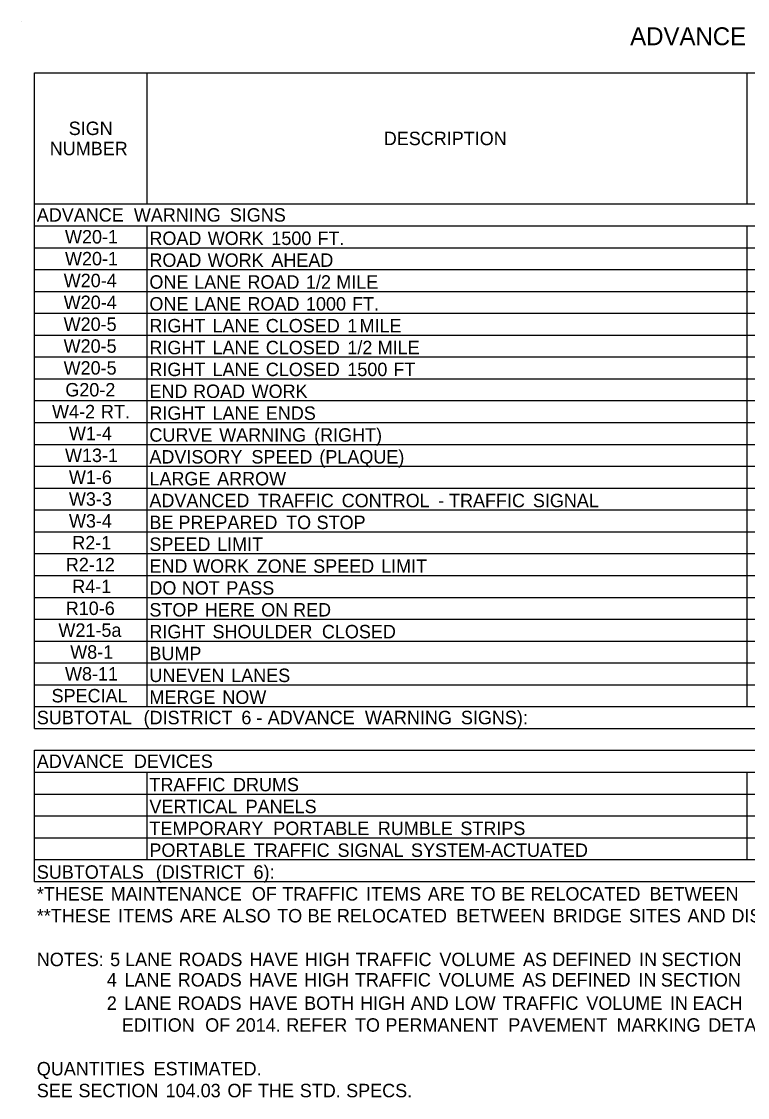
# Model space of a CAD drawing. Extents: x 542596 to 1930787, y -1948294 to 596640.
# Drawn here: x 544502.6 to 544826.4, y -1945630.8 to -1945150.8 of the extents above; entities that cross this region are included whole.
import ezdxf

# ---------------------------------------------------------------- set-up
doc = ezdxf.new("R2010")
doc.units = 0
doc.layers.add('Default', color=7, linetype='Continuous')

msp = doc.modelspace()

# ---------------------------------------------------------------- linework, layer by layer
at = {"layer": 'Default'}
for p, q in [((544502.61, -1945150.75), (544502.61, -1945150.75)), ((544508.46, -1945173.66), (545412.28, -1945173.66)), ((544508.46, -1945466.16), (544508.46, -1945173.66)), ((544508.46, -1945466.16), (544508.46, -1945173.66)), ((544558.67, -1945232.16), (544558.67, -1945173.66)), ((544826.31, -1945232.16), (544826.31, -1945173.66)), ((544508.46, -1945232.16), (545412.28, -1945232.16)), ((544508.46, -1945241.91), (545412.28, -1945241.91)), ((544558.67, -1945456.41), (544558.67, -1945241.91)), ((544558.67, -1945456.41), (544558.67, -1945241.91)), ((544826.31, -1945456.41), (544826.31, -1945241.91)), ((544826.31, -1945456.41), (544826.31, -1945241.91)), ((544508.46, -1945251.66), (545412.28, -1945251.66)), ((544508.46, -1945261.41), (545412.28, -1945261.41)), ((544508.46, -1945271.16), (545412.28, -1945271.16)), ((544508.46, -1945280.91), (545412.28, -1945280.91)), ((544508.46, -1945290.66), (545412.28, -1945290.66)), ((544508.46, -1945300.41), (545412.28, -1945300.41)), ((544508.46, -1945310.16), (545412.28, -1945310.16)), ((544508.46, -1945319.91), (545412.28, -1945319.91)), ((544508.46, -1945329.66), (545412.28, -1945329.66)), ((544508.46, -1945339.41), (545412.28, -1945339.41)), ((544508.46, -1945349.16), (545412.28, -1945349.16)), ((544508.46, -1945358.91), (545412.28, -1945358.91)), ((544508.46, -1945368.66), (545412.28, -1945368.66)), ((544508.46, -1945378.41), (545412.28, -1945378.41)), ((544508.46, -1945388.16), (545412.28, -1945388.16)), ((544508.46, -1945397.91), (545412.28, -1945397.91)), ((544508.46, -1945407.66), (545412.28, -1945407.66)), ((544508.46, -1945417.41), (545412.28, -1945417.41)), ((544508.46, -1945427.16), (545412.28, -1945427.16)), ((544508.46, -1945436.91), (545412.28, -1945436.91)), ((544508.46, -1945446.66), (545412.28, -1945446.66)), ((544508.46, -1945456.41), (545412.28, -1945456.41)), ((544508.46, -1945466.16), (545412.28, -1945466.16)), ((544508.46, -1945475.91), (545412.28, -1945475.91)), ((544508.46, -1945534.41), (544508.46, -1945475.91)), ((544508.46, -1945534.41), (544508.46, -1945475.91)), ((544558.67, -1945475.91), (545324.53, -1945475.91)), ((544508.46, -1945485.66), (545412.28, -1945485.66)), ((544558.67, -1945524.66), (544558.67, -1945485.66)), ((544558.67, -1945524.66), (544558.67, -1945485.66)), ((544826.31, -1945524.66), (544826.31, -1945485.66)), ((544826.31, -1945524.66), (544826.31, -1945485.66)), ((544508.46, -1945495.41), (545412.28, -1945495.41)), ((544508.46, -1945505.16), (545412.28, -1945505.16)), ((544508.46, -1945514.91), (545412.28, -1945514.91)), ((544508.46, -1945524.66), (545412.28, -1945524.66)), ((544508.46, -1945524.66), (545412.28, -1945524.66)), ((544508.46, -1945534.41), (545412.28, -1945534.41))]:
    msp.add_line(p, q, dxfattribs=at)

# ---------------------------------------------------------------- texts
for s, height, p in [('ADVANCE', 8, (544774.08, -1945161.33)), ('SIGN', 6, (544523.65, -1945201.41)), ('DESCRIPTION', 6, (544664.18, -1945205.91)), ('NUMBER', 6, (544515.19, -1945210.41)), ('ADVANCE', 6, (544509.43, -1945240.04)), (' WARNING', 6, (544550.48, -1945240.04)), (' SIGNS', 6, (544593.28, -1945240.04)), ('W20-1', 6, (544522, -1945249.79)), ('ROAD', 6, (544559.65, -1945250.46)), (' WORK', 6, (544583.42, -1945250.46)), (' 1500', 6, (544611.81, -1945250.46)), (' FT.', 6, (544632.38, -1945250.46)), ('W20-1', 6, (544522, -1945259.54)), ('ROAD', 6, (544559.65, -1945260.21)), (' WORK', 6, (544583.42, -1945260.21)), (' AHEAD', 6, (544611.81, -1945260.21)), ('W20-4', 6, (544521.43, -1945269.29)), ('ONE', 6, (544559.65, -1945269.96)), (' LANE', 6, (544577.37, -1945269.96)), (' ROAD', 6, (544601.15, -1945269.96)), (' 1/2', 6, (544627.25, -1945269.96)), (' MILE', 6, (544640.78, -1945269.96)), ('W20-4', 6, (544521.43, -1945279.04)), ('ONE', 6, (544559.65, -1945279.71)), (' LANE', 6, (544577.37, -1945279.71)), (' ROAD', 6, (544601.15, -1945279.71)), (' 1000', 6, (544627.25, -1945279.71)), (' FT.', 6, (544647.82, -1945279.71)), ('W20-5', 6, (544521.39, -1945288.79)), ('RIGHT', 6, (544559.65, -1945289.46)), (' LANE', 6, (544585.56, -1945289.46)), (' CLOSED', 6, (544609.34, -1945289.46)), (' 1', 6, (544645.7, -1945289.46)), (' MILE', 6, (544651.14, -1945289.46)), ('W20-5', 6, (544521.39, -1945298.54)), ('RIGHT', 6, (544559.65, -1945299.21)), (' LANE', 6, (544585.56, -1945299.21)), (' CLOSED', 6, (544609.34, -1945299.21)), (' 1/2', 6, (544645.7, -1945299.21)), (' MILE', 6, (544659.23, -1945299.21)), ('W20-5', 6, (544521.39, -1945308.29)), ('RIGHT', 6, (544559.65, -1945308.96)), (' LANE', 6, (544585.56, -1945308.96)), (' CLOSED', 6, (544609.34, -1945308.96)), (' 1500', 6, (544645.7, -1945308.96)), (' FT', 6, (544666.26, -1945308.96)), ('G20-2', 6, (544522.14, -1945318.04)), ('END', 6, (544559.65, -1945318.71)), (' ROAD', 6, (544576.9, -1945318.71)), (' WORK', 6, (544603.01, -1945318.71)), ('W4-2', 6, (544516.23, -1945327.79)), (' RT.', 6, (544535.8, -1945327.79)), ('RIGHT', 6, (544559.65, -1945328.46)), (' LANE', 6, (544585.56, -1945328.46)), (' ENDS', 6, (544609.34, -1945328.46)), ('W1-4', 6, (544523.76, -1945337.54)), ('CURVE', 6, (544559.65, -1945338.21)), (' WARNING', 6, (544588.55, -1945338.21)), (' (RIGHT)', 6, (544630.87, -1945338.21)), ('W13-1', 6, (544522, -1945347.29)), ('ADVISORY', 6, (544559.65, -1945347.96)), (' SPEED', 6, (544602.91, -1945347.96)), (' (PLAQUE)', 6, (544633.22, -1945347.96)), ('W1-6', 6, (544523.74, -1945357.04)), ('LARGE', 6, (544559.65, -1945357.71)), (' ARROW', 6, (544587.62, -1945357.71)), ('W3-3', 6, (544523.74, -1945366.79)), ('ADVANCED', 6, (544559.65, -1945367.46)), (' TRAFFIC', 6, (544605.79, -1945367.46)), (' CONTROL', 6, (544643.18, -1945367.46)), (' TRAFFIC', 6, (544691.06, -1945367.46)), (' SIGNAL', 6, (544728.45, -1945367.46)), (' -', 6, (544686.2, -1945367.46)), ('W3-4', 6, (544523.76, -1945376.54)), ('BE', 6, (544559.65, -1945377.21)), (' PREPARED', 6, (544570.38, -1945377.21)), (' TO', 6, (544618.39, -1945377.21)), (' STOP', 6, (544631.99, -1945377.21)), ('R2-1', 6, (544525.25, -1945386.29)), ('SPEED', 6, (544559.65, -1945386.96)), (' LIMIT', 6, (544587.63, -1945386.96)), ('R2-12', 6, (544522.38, -1945396.04)), ('END', 6, (544559.65, -1945396.71)), (' WORK', 6, (544576.9, -1945396.71)), (' ZONE', 6, (544605.29, -1945396.71)), (' SPEED', 6, (544630.46, -1945396.71)), (' LIMIT', 6, (544660.77, -1945396.71)), ('R4-1', 6, (544525.25, -1945405.79)), ('DO', 6, (544559.65, -1945406.46)), (' NOT', 6, (544571.85, -1945406.46)), (' PASS', 6, (544591.71, -1945406.46)), ('R10-6', 6, (544522.34, -1945415.54)), ('STOP', 6, (544559.65, -1945416.21)), (' HERE', 6, (544582.11, -1945416.21)), (' ON', 6, (544607.29, -1945416.21)), (' RED', 6, (544621.5, -1945416.21)), ('W21-5a', 6, (544519.07, -1945425.29)), ('RIGHT', 6, (544559.65, -1945425.96)), (' SHOULDER', 6, (544585.56, -1945425.96)), (' CLOSED', 6, (544634.36, -1945425.96)), ('W8-1', 6, (544524.33, -1945435.04)), ('BUMP', 6, (544559.65, -1945435.71)), ('W8-11', 6, (544522, -1945444.79)), ('UNEVEN', 6, (544559.65, -1945445.46)), (' LANES', 6, (544593.9, -1945445.46)), ('SPECIAL', 6, (544516.01, -1945454.54)), ('MERGE', 6, (544559.65, -1945455.21)), (' NOW', 6, (544589.94, -1945455.21)), ('SUBTOTAL', 6, (544509.43, -1945464.29)), (' (DISTRICT', 6, (544554.83, -1945464.29)), (' 6', 6, (544598.43, -1945464.29)), (' ADVANCE', 6, (544610.18, -1945464.29)), (' WARNING', 6, (544653.55, -1945464.29)), (' SIGNS):', 6, (544696.35, -1945464.29)), (' -', 6, (544605.12, -1945464.29)), ('ADVANCE', 6, (544509.43, -1945483.79)), (' DEVICES', 6, (544550.48, -1945483.79)), ('TRAFFIC', 6, (544559.65, -1945494.21)), (' DRUMS', 6, (544594.71, -1945494.21)), ('VERTICAL', 6, (544559.65, -1945503.96)), (' PANELS', 6, (544600.35, -1945503.96)), ('TEMPORARY', 6, (544559.65, -1945513.71)), (' PORTABLE', 6, (544612.69, -1945513.71)), (' RUMBLE', 6, (544659.3, -1945513.71)), (' STRIPS', 6, (544696.12, -1945513.71)), ('PORTABLE', 6, (544559.65, -1945523.46)), (' TRAFFIC', 6, (544603.93, -1945523.46)), (' SIGNAL', 6, (544641.32, -1945523.46)), (' SYSTEM-ACTUATED', 6, (544674.1, -1945523.46)), ('SUBTOTALS', 6, (544509.43, -1945533.21)), (' (DISTRICT', 6, (544560.26, -1945533.21)), (' 6):', 6, (544603.86, -1945533.21)), ('*THESE', 6, (544509.43, -1945542.96)), (' MAINTENANCE', 6, (544540.2, -1945542.96)), (' OF', 6, (544603.11, -1945542.96)), (' TRAFFIC', 6, (544616.69, -1945542.96)), (' ITEMS', 6, (544654.08, -1945542.96)), (' ARE', 6, (544681.59, -1945542.96)), (' TO', 6, (544700.71, -1945542.96)), (' BE', 6, (544714.31, -1945542.96)), (' RELOCATED', 6, (544727.37, -1945542.96)), (' BETWEEN', 6, (544780.5, -1945542.96)), ('**THESE', 6, (544509.43, -1945552.71)), (' ITEMS', 6, (544543.46, -1945552.71)), (' ARE', 6, (544570.97, -1945552.71)), (' ALSO', 6, (544590.09, -1945552.71)), (' TO', 6, (544614.41, -1945552.71)), (' BE', 6, (544628.01, -1945552.71)), (' RELOCATED', 6, (544641.07, -1945552.71)), (' BETWEEN', 6, (544694.2, -1945552.71)), (' BRIDGE', 6, (544737.3, -1945552.71)), (' SITES', 6, (544771.33, -1945552.71)), (' AND', 6, (544797.44, -1945552.71)), (' DISTRICTS', 6, (544817.03, -1945552.71)), ('NOTES:', 6, (544509.43, -1945572.21)), (' 5', 6, (544539.91, -1945572.21)), (' LANE', 6, (544546.57, -1945572.21)), (' ROADS', 6, (544570.35, -1945572.21)), (' HAVE', 6, (544602.06, -1945572.21)), (' HIGH', 6, (544626.77, -1945572.21)), (' TRAFFIC', 6, (544649.38, -1945572.21)), (' VOLUME', 6, (544686.77, -1945572.21)), (' AS', 6, (544724.05, -1945572.21)), (' DEFINED', 6, (544737.13, -1945572.21)), (' IN', 6, (544775.81, -1945572.21)), (' SECTION', 6, (544785.83, -1945572.21)), ('              4', 6, (544509.43, -1945581.29)), (' LANE', 6, (544546.28, -1945581.29)), (' ROADS', 6, (544570.06, -1945581.29)), (' HAVE', 6, (544601.76, -1945581.29)), (' HIGH', 6, (544626.48, -1945581.29)), (' TRAFFIC', 6, (544649.09, -1945581.29)), (' VOLUME', 6, (544686.48, -1945581.29)), (' AS', 6, (544723.76, -1945581.29)), (' DEFINED', 6, (544736.84, -1945581.29)), (' IN', 6, (544775.52, -1945581.29)), (' SECTION', 6, (544785.54, -1945581.29)), ('              2', 6, (544509.43, -1945591.71)), (' LANE', 6, (544546.24, -1945591.71)), (' ROADS', 6, (544570.02, -1945591.71)), (' HAVE', 6, (544601.73, -1945591.71)), (' BOTH', 6, (544626.44, -1945591.71)), (' HIGH', 6, (544651.38, -1945591.71)), (' AND', 6, (544673.99, -1945591.71)), (' LOW', 6, (544693.57, -1945591.71)), (' TRAFFIC', 6, (544714.9, -1945591.71)), (' VOLUME', 6, (544752.29, -1945591.71)), (' IN', 6, (544789.57, -1945591.71)), (' EACH', 6, (544799.6, -1945591.71)), ('                 EDITION', 6, (544509.43, -1945601.46)), (' OF', 6, (544582.32, -1945601.46)), (' 2014.', 6, (544595.91, -1945601.46)), (' REFER', 6, (544618.47, -1945601.46)), (' TO', 6, (544649.1, -1945601.46)), (' PERMANENT', 6, (544662.7, -1945601.46)), (' PAVEMENT', 6, (544717.5, -1945601.46)), (' MARKING', 6, (544765.78, -1945601.46)), (' DETAILS', 6, (544806.71, -1945601.46)), ('QUANTITIES', 6, (544509.43, -1945620.96)), (' ESTIMATED.', 6, (544559.31, -1945620.96)), ('SEE', 6, (544509.43, -1945630.71)), (' SECTION', 6, (544525.77, -1945630.71)), (' 104.03', 6, (544564.67, -1945630.71)), (' OF', 6, (544592.25, -1945630.71)), (' THE', 6, (544605.84, -1945630.71)), (' STD.', 6, (544624.49, -1945630.71)), (' SPECS.', 6, (544645.18, -1945630.71))]:
    msp.add_text(s, height=height, dxfattribs=at).set_placement(p)

doc.saveas('drawing.dxf')
